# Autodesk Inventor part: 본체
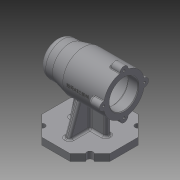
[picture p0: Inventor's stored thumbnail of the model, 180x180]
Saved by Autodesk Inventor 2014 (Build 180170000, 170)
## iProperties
Created: 2021-01
Part Number: 본체
Material: Generic
Document SubType Name: Modeling
Designer: kh
Density: 1 g/cm^3
Appearance: Default
Author: kh
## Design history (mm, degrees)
sketch "Sketch1" dims "d0" = 100
  geometry: L1 (20.711, 50)-(50, 20.711); L2 (50, 20.711)-(50, -20.711); L3 (50, -20.711)-(20.711, -50); L4 (20.711, -50)-(-20.711, -50); L5 (-20.711, -50)-(-50, -20.711); L6 (-50, -20.711)-(-50, 20.711); L7 (-50, 20.711)-(-20.711, 50); L8 (-20.711, 50)-(20.711, 50); L9 (0, 0)-(0, 50); 4 further points
  constraints: 18 end point, 3 coincident, 1 midpoint, 1 vertical, 20 other
  dimensions: "d12" = 50 distance of L9.start L9.end
extrude "Extrusion1" new body sketch "Sketch1" distance "d1" = 10; taper "d2" = 0 deg
workplane "Work Plane1"
sketch "Sketch2"
  geometry: L1 (-19.134, 0)-(19.134, 0) reference; L2 (-19.134, 0)-(-19.134, 10) reference; L3 (19.134, 10)-(-19.134, 10) reference; L4 (19.134, 0)-(19.134, 10) reference; L5 (-46.194, 0)-(-19.134, 0) reference; L6 (-46.194, 0)-(-46.194, 10) reference; L7 (-19.134, 10)-(-46.194, 10) reference; L8 (-19.134, 0)-(-19.134, 10) reference; L9 (19.134, 0)-(46.194, 0) reference; L10 (19.134, 0)-(19.134, 10) reference; L11 (46.194, 10)-(19.134, 10) reference; L12 (46.194, 0)-(46.194, 10) reference; L13 (-50, 75)-(-30, 75); L14 (-30, 75)-(-30, 100); L15 (-30, 100)-(-50, 100); L16 (-50, 100)-(-50, 75); L17 (-30, 75)-(-10, 75); L18 (-10, 75)-(-10, 105); L19 (-30, 100)-(-30, 75); L20 (-10, 75)-(50, 75); L21 (50, 75)-(50, 105); L22 (50, 105)-(-10, 105); L23 (-10, 105)-(-10, 75); L24 (-30, 100)-(-10, 105); L25 (-50, 0)-(-20.711, 0) reference; L26 (-50, 0)-(-50, 10) reference; L27 (-20.711, 10)-(-50, 10) reference; L28 (-20.711, 0)-(-20.711, 10) reference; L29 (-20.711, 0)-(20.711, 0) reference; L30 (-20.711, 0)-(-20.711, 10) reference; L31 (20.711, 10)-(-20.711, 10) reference; L32 (20.711, 0)-(20.711, 10) reference; L33 (20.711, 0)-(50, 0) reference; L34 (20.711, 0)-(20.711, 10) reference; L35 (50, 10)-(20.711, 10) reference; L36 (50, 0)-(50, 10) reference
  constraints: 24 end point, 5 parallel, 3 horizontal, 3 perpendicular, 1 collinear
  dimensions: "d5" = 50 diameter of L15 L13; "d7" = 60 diameter of L22 L20; "d8" = 100 distance between parallel lines of L21 L16; "d9" = 40 distance between parallel lines of L16 L18; "d10" = 20 distance between parallel lines of L16 L14; "d14" = 75 distance of L13.start L25.start
revolve "Revolution2" sketch "Sketch2" stored, may be unused: angle "d15" = 90 deg
workplane "Work Plane2"
sketch "Sketch3"
  geometry: L1 (-50, 50)-(-50, 100) reference; L2 (50, 45)-(50, 105) reference; L3 (-50, 75)-(50, 75); L4 (50, 75)-(35, 75); L5 (35, 75)-(35, 96); L6 (35, 96)-(50, 96); L7 (50, 96)-(50, 75); L8 (35, 75)-(-7, 75); L9 (-7, 75)-(-7, 99); L10 (-7, 99)-(35, 99); L11 (35, 99)-(35, 75); L12 (-7, 75)-(-19, 75); L13 (-19, 75)-(-19, 96); L14 (-19, 96)-(-7, 96); L15 (-7, 96)-(-7, 75); L16 (-19, 75)-(-37, 75); L17 (-37, 75)-(-37, 92.5); L18 (-37, 92.5)-(-19, 92.5); L19 (-19, 92.5)-(-19, 75); L20 (-37, 75)-(-41, 75); L21 (-41, 75)-(-41, 91); L22 (-41, 91)-(-37, 91); L23 (-37, 91)-(-37, 75); L24 (-41, 75)-(-44, 75); L25 (-44, 75)-(-44, 85.5); L26 (-44, 85.5)-(-41, 85.5); L27 (-41, 85.5)-(-41, 75); 1 further point
  constraints: 50 end point, 12 parallel, 6 horizontal, 6 perpendicular, 2 midpoint
  dimensions: "d17" = 15 distance between parallel lines of L5 L7; "d18" = 42 distance between parallel lines of L15 L5; "d19" = 12 distance between parallel lines of L13 L15; "d20" = 18 distance between parallel lines of L17 L13; "d21" = 4 distance between parallel lines of L17 L21; "d22" = 3 distance between parallel lines of L21 L25; "d23" = 42 diameter of L6 L3; "d24" = 48 diameter of L10 L3; "d25" = 42 diameter of L14 L12; "d26" = 35 diameter of L18 L16; "d27" = 32 diameter of L22 L3; "d28" = 21 diameter of L26 L24
revolve "Revolution3" sketch "Sketch3" stored, may be unused: angle "d29" = 90 deg
fillet "Fillet1" dims "d30" = 0.3
fillet "Fillet2" dims "d31" = 3
fillet "Fillet3" dims "d32" = 3
chamfer "Chamfer1" distance "d33" = 1; stored, may be unused: second distance "d34" = 2, angle "d35" = 45 deg
sketch "Sketch4" dims "d36" = 60
  geometry: L1 (0, 0)-(0, -34.728); C1 r 25 at (0, 0) reference; C2 r 30 at (0, 0) reference; C3 r 6 at (0, -30); 2 further points
  constraints: 2 coincident, 2 end point, 1 centre point, 1 point on line, 1 vertical, 1 vertical alignment, 2 other
  dimensions: "d37" = 12 diameter of C3
extrude "Extrusion2" join sketch "Sketch4" distance "d38" = 16; taper "d39" = 0 deg
pattern_circular "Circular Pattern1" dims angle "d41" = 360 deg
sketch "Sketch5"
  geometry: C1 r 22 at (0, 30) reference; A1 r 30 centre (0, 30) between (-29.4, 24.03) and (-5.97, 0.6) reference; A2 r 6 centre (0, 0) between (-5.97, 0.6) and (5.97, 0.6) reference; A3 r 30 centre (0, 30) between (5.97, 0.6) and (29.4, 24.03) reference; A4 r 6 centre (30, 30) between (29.4, 24.03) and (29.4, 35.97) reference; A5 r 30 centre (0, 30) between (29.4, 35.97) and (5.97, 59.4) reference; A6 r 6 centre (0, 60) between (5.97, 59.4) and (-5.97, 59.4) reference; A7 r 30 centre (0, 30) between (-5.97, 59.4) and (-29.4, 35.97) reference; A8 r 6 centre (-30, 30) between (-29.4, 35.97) and (-29.4, 24.03) reference; 5 further points
  constraints: 4 coincident
hole "Hole1" sketch "Sketch5" at (0, 0), (30, 30), (0, 60), (-30, 30) diameter "d43" = 3.242; stored, may be unused: countersink angle "d47" = 90 deg, drill point angle "d49" = 118 deg; dims "d44" = 8, "d45" = 4, "d46" = 2, "d48" = 10
sketch "Sketch6"
  geometry: L1 (20.711, 50)-(50, 20.711) reference; L2 (50, 20.711)-(50, -20.711) reference; L3 (50, -20.711)-(20.711, -50) reference; L4 (20.711, -50)-(-20.711, -50) reference; L5 (-20.711, -50)-(-50, -20.711) reference; L6 (-50, -20.711)-(-50, 20.711) reference; L7 (-50, 20.711)-(-20.711, 50) reference; L8 (-20.711, 50)-(20.711, 50) reference; L9 (0, 0)-(-35.355, -35.355); L10 (0, 0)-(-50, 0); L11 (0, 0)-(-35.355, 35.355); L12 (0, 0)-(35.355, -35.355); L13 (0, 0)-(35.355, 35.355); A1 r 50 centre (0, 0) between (-35.355, -35.355) and (-50, 0); 5 further points
  constraints: 10 end point, 5 coincident, 5 midpoint, 5 point on circle, 1 centre point
  dimensions: "d50" = 100 diameter of A1
hole "Hole2" sketch "Sketch6" at (-35.355, -35.355), (-35.355, 35.355), (35.355, 35.355), (35.355, -35.355) diameter "d51" = 9; stored, may be unused: countersink angle "d55" = 90 deg, drill point angle "d57" = 118 deg; dims "d52" = 8, "d53" = 4, "d54" = 2, "d56" = 10
sketch "Sketch7"
  geometry: L1 (38.537, 32.173)-(50, 20.711) reference; L2 (50, 20.711)-(50, -20.711) reference; L3 (50, -20.711)-(38.537, -32.173) reference; L4 (32.173, -38.537)-(20.711, -50) reference; L5 (20.711, -50)-(-20.711, -50) reference; L6 (-20.711, -50)-(-32.173, -38.537) reference; L7 (-38.537, -32.173)-(-50, -20.711) reference; L8 (-50, -20.711)-(-50, 20.711) reference; L9 (-50, 20.711)-(-38.537, 32.173) reference; L10 (-32.173, 38.537)-(-20.711, 50) reference; L11 (-20.711, 50)-(20.711, 50) reference; L12 (20.711, 50)-(32.173, 38.537) reference; L13 (4, -4)-(-4, -4); L14 (-4, -4)-(-4, 4); L15 (-4, 4)-(4, 4); L16 (4, 4)-(4, -4); L17 (4, -4)-(-4, 4); L18 (-4, -4)-(4, 4); L19 (4, 4)-(-4, 4); L20 (-4, 4)-(-4, 27); L21 (-4, 27)-(4, 27); L22 (4, 27)-(4, 4); A1 r 4.5 centre (35.355, 35.355) between (32.173, 38.537) and (38.537, 32.173) reference; A2 r 4.5 centre (35.355, -35.355) between (38.537, -32.173) and (32.173, -38.537) reference; A3 r 4.5 centre (-35.355, -35.355) between (-32.173, -38.537) and (-38.537, -32.173) reference; A4 r 4.5 centre (-35.355, 35.355) between (-38.537, 32.173) and (-32.173, 38.537) reference; 1 further point
  constraints: 20 end point, 4 parallel, 2 horizontal, 2 midpoint, 2 perpendicular, 1 collinear
  dimensions: "d58" = 8 distance of L13.end L14.end; "d59" = 8 distance of L14.end L15.end; "d89" = 23 distance between parallel lines of L21 L11
  node "Projected Loop10"
extrude "Extrusion3" join sketch "Sketch7" stored distance "d60" = 16; taper "d61" = 0 deg
workplane "Work Plane3"
sketch "Sketch8"
  geometry: L1 (-50, 0)-(-50, 10) reference; L2 (-38.537, 10)-(-50, 10) reference; L3 (50, 10)-(38.537, 10) reference; L4 (50, 0)-(50, 10) reference; L5 (-35, 10)-(-22.074, 45.513); L6 (35, 10)-(22.341, 44.781); 1 further point
  constraints: 4 end point, 2 point on line
  dimensions: "d64" = 110 deg angle of L2 L5; "d65" = 15 distance from line of L5.start L1; "d66" = 110 deg angle of L6 L3; "d67" = 15 distance of L6.start L3.start
feature "Rib1" dims "d68" = 1, "d69" = 8, "d70" = 0, "d71" = 0, "d72" = 1, "d73" = 1
feature "Rib2" dims "d74" = 1, "d75" = 8, "d76" = 0, "d77" = 0, "d78" = 1, "d79" = 1
workplane "Work Plane4"
sketch "Sketch9"
  geometry: L1 (-38.537, 10)-(-50, 10) reference; L2 (-38.537, 10)-(-30.855, 10) reference; L3 (-20.711, 10)-(-32.173, 10) reference; L4 (-50, 0)-(-50, 10) reference; L5 (-27, 10)-(-20.559, 43.137); 1 further point
  constraints: 2 end point, 1 point on line
  dimensions: "d81" = 101 deg angle of L5 L1; "d82" = 23 distance from line of L5.start L4
feature "Rib3" sketch "Sketch9" dims "d83" = 1, "d84" = 8, "d85" = 0, "d86" = 0, "d87" = 1, "d88" = 1
extrude "Extrusion4" join sketch "Sketch7" stored distance "d90" = 16; taper "d91" = 0 deg
fillet "Fillet4" dims "d92" = 10
fillet "Fillet5" dims "d93" = 3
fillet "Fillet6" dims "d94" = 1
fillet "Fillet7" dims "d95" = 3
fillet "Fillet8" dims "d96" = 3
fillet "Fillet9" dims "d97" = 3
workplane "Work Plane5"
sketch "Sketch11"
  geometry: L1 (-24.592, 2.402)-(8.592, 2.402); L2 (8.592, 2.402)-(8.592, -2.402); L3 (8.592, -2.402)-(-24.592, -2.402); L4 (-24.592, -2.402)-(-24.592, 2.402); L5 (-24.592, 0)-(8.592, 0); L6 (-8, 2.402)-(-8, -2.402); L7 (30, 6.771)-(30, 29.226) reference; L8 (-70, -15)-(-70, 15) reference; L9 (-70, 0)-(30, 0); 1 further point
  constraints: 6 end point, 5 midpoint, 1 collinear, 1 perpendicular, 2 other
  dimensions: "d98" = 38 distance between parallel lines of L7 L6
emboss "Emboss1" sketch "Sketch11" dims "d0" = 100, "d5" = 50, "d7" = 60, "d8" = 100, "d9" = 40, "d10" = 20, "d12" = 50, "d14" = 75, "d99" = 0.5, "d100" = 0
body "Solid1"
node "Projected Loop1"
node "Projected Loop2"
node "Projected Loop3"
node "Projected Loop4"
node "Projected Loop5"
node "Projected Loop6"
node "Projected Loop7"
node "Projected Loop8"
node "Projected Loop9"
other parameters: "d3" = 0, "d16" = 0, "d62" = 0, "d80" = 0
